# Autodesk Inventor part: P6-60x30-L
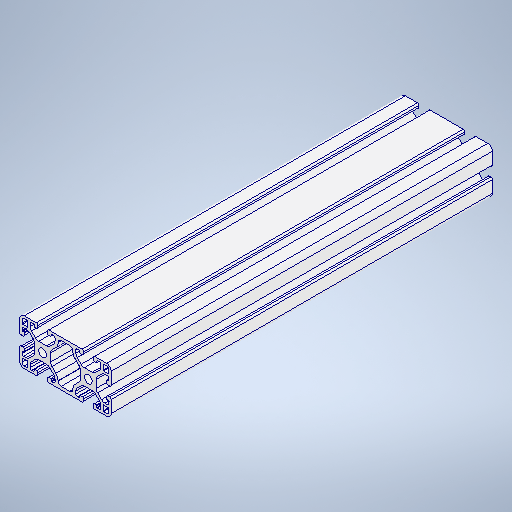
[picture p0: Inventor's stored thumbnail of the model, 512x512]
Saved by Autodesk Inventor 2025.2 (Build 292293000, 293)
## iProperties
Created: 2017-03
Part Number: P6-60x30-L
Material: Generic
Description: Aluminium eloxiert RAL 9006
Document SubType Name: Modeling
Designer: Jarni
Density: 1 g/cm^3
Appearance: Default
Sending System: Autodesk Inventor 2015
Preprocessor: ST-DEVELOPER v15.6
Title: C:\Users\Public\VaultWorkspace\Designs\Katalogteile\P6-60x30-L\P6-60x30-L.stp
Author: dt
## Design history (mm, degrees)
node "Volumenkörper1"
thicken "Thicken1" dims "d0" = 50, "d1" = 50
body "Solid1"
